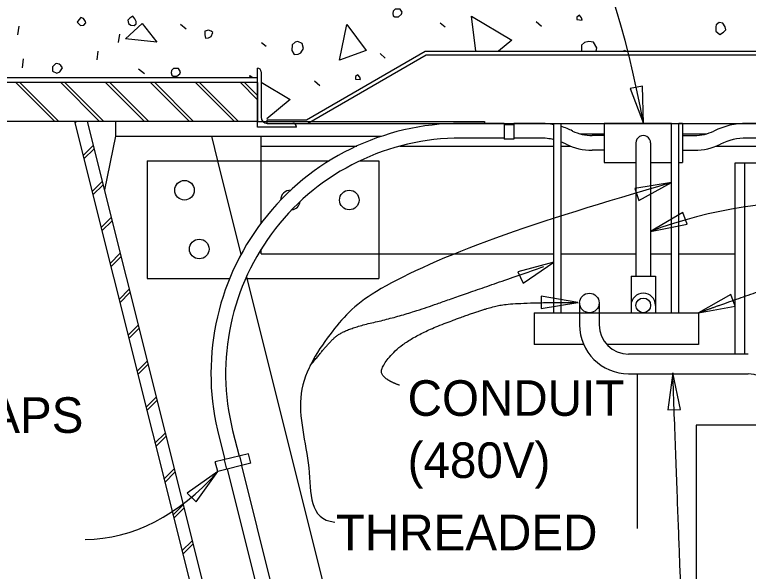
# Model space of a CAD drawing. Extents: x -1660015.2 to -1659984.9, y 2580594.2 to 2580616.7.
# Drawn here: x -1660013.123 to -1660010.005, y 2580601.136 to 2580603.502 of the extents above; entities that cross this region are included whole.
import ezdxf

# ---------------------------------------------------------------- set-up
doc = ezdxf.new("R2010")
doc.units = 0
for name, color, linetype in [('Default', 7, 'Continuous'), ('Miscellaneous', 7, 'Continuous'), ('SheetLines_dp', 7, 'Continuous'), ('SteelGirder', 7, 'Continuous')]:
    doc.layers.add(name, color=color, linetype=linetype)

msp = doc.modelspace()

# ---------------------------------------------------------------- linework, layer by layer
at = {"layer": 'Default'}
for p, q in [((-1660011.0429, 2580603.0403), (-1660011.2268, 2580603.0403)), ((-1660010.8905, 2580603.0403), (-1660011.0012, 2580603.0403)), ((-1660010.6182, 2580603.0404), (-1660010.6182, 2580602.8737)), ((-1660010.3317, 2580603.0404), (-1660010.6182, 2580603.0404)), ((-1660010.2849, 2580603.0404), (-1660010.3005, 2580603.0404)), ((-1660010.2849, 2580603.0404), (-1660010.2849, 2580602.8737)), ((-1660009.6587, 2580603.0404), (-1660010.0129, 2580603.0404)), ((-1660011.0429, 2580602.9779), (-1660011.2268, 2580602.9779)), ((-1660010.8902, 2580602.9779), (-1660011.0012, 2580602.9779)), ((-1660010.6182, 2580602.9883), (-1660010.6686, 2580602.9883)), ((-1660010.2849, 2580602.9883), (-1660010.2345, 2580602.9883)), ((-1660009.6587, 2580602.9779), (-1660010.013, 2580602.9779)), ((-1660012.0762, 2580602.6162), (-1660012.0762, 2580602.9437)), ((-1660010.4828, 2580602.957), (-1660010.4828, 2580602.3908)), ((-1660010.4203, 2580602.957), (-1660010.4203, 2580602.3908)), ((-1660010.6182, 2580602.9258), (-1660010.6686, 2580602.9258)), ((-1660010.2849, 2580602.9258), (-1660010.2345, 2580602.9258)), ((-1660012.2611, 2580602.8812), (-1660012.1615, 2580602.4831)), ((-1660010.6182, 2580602.8737), (-1660010.4828, 2580602.8737)), ((-1660010.4203, 2580602.8737), (-1660010.3317, 2580602.8737)), ((-1660010.3005, 2580602.8737), (-1660010.2849, 2580602.8737)), ((-1660010.0631, 2580602.8708), (-1660010.0631, 2580602.0589)), ((-1660009.9277, 2580602.8708), (-1660010.0631, 2580602.8708)), ((-1660010.0215, 2580602.8708), (-1660010.0215, 2580602.0589)), ((-1660012.0762, 2580602.4853), (-1660012.0762, 2580602.5057)), ((-1660012.0762, 2580602.4853), (-1660011.5762, 2580602.4853)), ((-1660012.1381, 2580602.3896), (-1660012.136, 2580602.3812)), ((-1660010.5036, 2580602.3908), (-1660010.3995, 2580602.3908)), ((-1660010.5036, 2580602.3908), (-1660010.5036, 2580602.2353)), ((-1660010.3995, 2580602.3908), (-1660010.3995, 2580602.2353)), ((-1660010.7223, 2580602.277), (-1660010.7223, 2580602.184)), ((-1660010.639, 2580602.277), (-1660010.639, 2580602.1841)), ((-1660010.9151, 2580602.2353), (-1660010.2172, 2580602.2353)), ((-1660010.9151, 2580602.2353), (-1660010.9151, 2580602.0999)), ((-1660010.2172, 2580602.2353), (-1660010.2172, 2580602.0999)), ((-1660010.7046, 2580602.0999), (-1660010.9151, 2580602.0999)), ((-1660010.2172, 2580602.0999), (-1660010.6064, 2580602.0999)), ((-1660010.0052, 2580602.0589), (-1660010.514, 2580602.0591)), ((-1660010.5141, 2580601.9757), (-1660010.0053, 2580601.9755)), ((-1660012.197, 2580601.7353), (-1660012.1697, 2580601.6264)), ((-1660012.2542, 2580601.7069), (-1660012.2303, 2580601.6112)), ((-1660012.2202, 2580601.5708), (-1660011.7218, 2580599.577)), ((-1660012.1596, 2580601.5859), (-1660011.6612, 2580599.5922))]:
    msp.add_line(p, q, dxfattribs=at)
msp.add_lwpolyline([(-1660009.2275, 2580601.7577), (-1660010.2275, 2580601.7577), (-1660010.2275, 2580599.0077), (-1660009.2275, 2580599.0077)], close=True, dxfattribs=at)
for centre, radius in [((-1660010.6807, 2580602.277), 0.0416), ((-1660010.4516, 2580602.2666), 0.0312)]:
    msp.add_circle(centre, radius, dxfattribs=at)
for centre, radius, start, end in [((-1660011.2268, 2580601.9779), 1.0625, 90.0002, 194.7729), ((-1660010.8908, 2580602.7279), 0.3125, 79.1097, 89.9466), ((-1660010.0123, 2580602.7279), 0.3125, 90.0002, 116.3886), ((-1660010.8908, 2580602.7279), 0.3125, 63.6116, 73.2157), ((-1660010.6686, 2580603.1758), 0.1875, 243.6116, 270.0001), ((-1660010.2345, 2580603.1758), 0.1875, 270.0001, 296.3886), ((-1660011.2268, 2580601.9779), 1, 90.0002, 194.0354), ((-1660010.8908, 2580602.7279), 0.25, 76.3399, 89.8674), ((-1660010.4516, 2580602.957), 0.0312, 359.9876, 180.0001), ((-1660010.0123, 2580602.7279), 0.25, 90.0002, 116.3886), ((-1660010.8908, 2580602.7279), 0.25, 63.6116, 68.8407), ((-1660010.6686, 2580603.1758), 0.25, 243.6116, 270.0001), ((-1660010.2345, 2580603.1758), 0.25, 270.0001, 296.3886), ((-1660010.4516, 2580602.2666), 0.052, 0.0163, 179.7051), ((-1660010.514, 2580602.184), 0.2083, 180, 269.9792), ((-1660010.514, 2580602.1841), 0.125, 180, 269.9792), ((-1660010.0053, 2580601.8505), 0.125, 0, 89.9792)]:
    msp.add_arc(centre, radius, start, end, dxfattribs=at)
at = {"layer": 'Miscellaneous'}
for p, q in [((-1660011.3147, 2580603.4678), (-1660011.2944, 2580603.4499)), ((-1660010.9073, 2580603.4734), (-1660010.8839, 2580603.4538)), ((-1660013.1101, 2580603.4164), (-1660013.1046, 2580603.454)), ((-1660012.4183, 2580603.4619), (-1660012.3949, 2580603.4423)), ((-1660012.682, 2580603.3835), (-1660012.6759, 2580603.4188)), ((-1660012.0737, 2580603.3835), (-1660012.0541, 2580603.368)), ((-1660012.7735, 2580603.3098), (-1660012.7681, 2580603.3475)), ((-1660011.8834, 2580603.0559), (-1660011.3782, 2580603.3476)), ((-1660011.3782, 2580603.3476), (-1660006.558, 2580603.3477)), ((-1660013.0907, 2580603.2766), (-1660013.0853, 2580603.3143)), ((-1660011.8792, 2580603.0403), (-1660011.374, 2580603.332)), ((-1660011.5696, 2580603.3374), (-1660011.5487, 2580603.3171)), ((-1660011.374, 2580603.332), (-1660006.558, 2580603.3321)), ((-1660012.5976, 2580603.2715), (-1660012.5718, 2580603.2526)), ((-1660012.0918, 2580603.0247), (-1660012.0917, 2580603.2747)), ((-1660012.0761, 2580603.2591), (-1660012.0761, 2580603.0664)), ((-1660013.5994, 2580603.2354), (-1660012.0917, 2580603.2354)), ((-1660011.849, 2580603.2211), (-1660011.8257, 2580603.2015)), ((-1660012.9534, 2580603.0479), (-1660013.1202, 2580603.2147)), ((-1660012.9358, 2580603.0479), (-1660013.1025, 2580603.2147)), ((-1660012.7625, 2580603.0479), (-1660012.9292, 2580603.2147)), ((-1660012.7449, 2580603.0479), (-1660012.9116, 2580603.2147)), ((-1660012.5716, 2580603.0479), (-1660012.7383, 2580603.2147)), ((-1660012.5539, 2580603.0479), (-1660012.7207, 2580603.2147)), ((-1660012.3807, 2580603.0479), (-1660012.5474, 2580603.2147)), ((-1660012.363, 2580603.0479), (-1660012.5297, 2580603.2147)), ((-1660012.1898, 2580603.0479), (-1660012.3565, 2580603.2147)), ((-1660012.1721, 2580603.0479), (-1660012.3388, 2580603.2147)), ((-1660012.0918, 2580603.1409), (-1660012.1656, 2580603.2147)), ((-1660012.0918, 2580603.1586), (-1660012.1479, 2580603.2147)), ((-1660012.8671, 2580603.0418), (-1660012.861, 2580603.0479)), ((-1660012.0501, 2580603.0559), (-1660011.8835, 2580603.0559)), ((-1660012.0501, 2580603.0403), (-1660012.0501, 2580603.0559)), ((-1660012.0501, 2580603.0403), (-1660006.558, 2580603.0403)), ((-1660012.0501, 2580603.0403), (-1660011.9407, 2580603.0403)), ((-1660011.9251, 2580603.0247), (-1660012.0918, 2580603.0247)), ((-1660012.8325, 2580602.9032), (-1660012.7895, 2580602.9462)), ((-1660012.829, 2580602.8891), (-1660012.786, 2580602.932)), ((-1660012.7943, 2580602.7505), (-1660012.7513, 2580602.7934)), ((-1660012.7908, 2580602.7363), (-1660012.7478, 2580602.7793)), ((-1660012.7561, 2580602.5977), (-1660012.7132, 2580602.6407)), ((-1660012.7526, 2580602.5836), (-1660012.7096, 2580602.6265)), ((-1660012.7179, 2580602.445), (-1660012.675, 2580602.488)), ((-1660012.7144, 2580602.4309), (-1660012.6714, 2580602.4738)), ((-1660012.6798, 2580602.2923), (-1660012.6368, 2580602.3352)), ((-1660012.6762, 2580602.2781), (-1660012.6333, 2580602.3211)), ((-1660012.6416, 2580602.1395), (-1660012.5986, 2580602.1825)), ((-1660012.638, 2580602.1254), (-1660012.5951, 2580602.1683)), ((-1660012.6034, 2580601.9868), (-1660012.5604, 2580602.0298)), ((-1660012.5998, 2580601.9726), (-1660012.5569, 2580602.0156)), ((-1660012.5652, 2580601.8341), (-1660012.5222, 2580601.877)), ((-1660012.5617, 2580601.8199), (-1660012.5187, 2580601.8629)), ((-1660012.527, 2580601.6813), (-1660012.4841, 2580601.7243)), ((-1660012.5235, 2580601.6672), (-1660012.4805, 2580601.7101)), ((-1660012.4888, 2580601.5286), (-1660012.4459, 2580601.5715)), ((-1660012.4853, 2580601.5144), (-1660012.4423, 2580601.5574)), ((-1660012.4506, 2580601.3758), (-1660012.4077, 2580601.4188)), ((-1660012.4471, 2580601.3617), (-1660012.4042, 2580601.4047)), ((-1660012.4125, 2580601.2231), (-1660012.3695, 2580601.2661)), ((-1660012.4089, 2580601.209), (-1660012.366, 2580601.2519))]:
    msp.add_line(p, q, dxfattribs=at)
for points in [[(-1660012.6391, 2580603.4649), (-1660012.6292, 2580603.4572), (-1660012.6159, 2580603.4556), (-1660012.6075, 2580603.463), (-1660012.6077, 2580603.4733), (-1660012.6133, 2580603.4847), (-1660012.6214, 2580603.4955), (-1660012.6346, 2580603.4868), (-1660012.643, 2580603.4794), (-1660012.6391, 2580603.4649)], [(-1660011.5141, 2580603.4972), (-1660011.508, 2580603.4936), (-1660011.4922, 2580603.4927), (-1660011.4796, 2580603.5038), (-1660011.4768, 2580603.5124), (-1660011.4855, 2580603.5255), (-1660011.5061, 2580603.5252), (-1660011.5144, 2580603.5178), (-1660011.5167, 2580603.5068), (-1660011.5141, 2580603.4972)], [(-1660011.1636, 2580603.3476), (-1660011.1824, 2580603.4955), (-1660011.0102, 2580603.3941), (-1660011.0665, 2580603.3476)], [(-1660010.7334, 2580603.4812), (-1660010.7121, 2580603.4791), (-1660010.7147, 2580603.4888), (-1660010.7228, 2580603.4996), (-1660010.7335, 2580603.4915), (-1660010.7334, 2580603.4812)], [(-1660012.8581, 2580603.4709), (-1660012.8439, 2580603.4566), (-1660012.8288, 2580603.4581), (-1660012.8211, 2580603.4679), (-1660012.8223, 2580603.4727), (-1660012.8311, 2580603.4859), (-1660012.8427, 2580603.4906), (-1660012.8504, 2580603.4808), (-1660012.8581, 2580603.4709)], [(-1660012.6525, 2580603.3992), (-1660012.5821, 2580603.4646), (-1660012.5195, 2580603.3857), (-1660012.6525, 2580603.3992)], [(-1660010.1428, 2580603.4505), (-1660010.1431, 2580603.4323), (-1660010.1265, 2580603.4186), (-1660010.1109, 2580603.428), (-1660010.1007, 2580603.4385), (-1660010.104, 2580603.4505), (-1660010.1133, 2580603.4662), (-1660010.1298, 2580603.4695), (-1660010.1423, 2580603.4584), (-1660010.1428, 2580603.4505)], [(-1660012.3157, 2580603.417), (-1660012.3118, 2580603.4025), (-1660012.299, 2580603.4033), (-1660012.2876, 2580603.409), (-1660012.2818, 2580603.426), (-1660012.2886, 2580603.432), (-1660012.3002, 2580603.4366), (-1660012.3147, 2580603.4328), (-1660012.3157, 2580603.417)], [(-1660011.7432, 2580603.309), (-1660011.7112, 2580603.4599), (-1660011.6299, 2580603.3497), (-1660011.7432, 2580603.309)], [(-1660011.9444, 2580603.3741), (-1660011.9458, 2580603.3504), (-1660011.9358, 2580603.3324), (-1660011.9183, 2580603.3345), (-1660011.9068, 2580603.3402), (-1660011.8962, 2580603.3585), (-1660011.9021, 2580603.3803), (-1660011.9198, 2580603.3885), (-1660011.9319, 2580603.3852), (-1660011.9444, 2580603.3741)], [(-1660010.6513, 2580603.3476), (-1660010.6495, 2580603.3613), (-1660010.6638, 2580603.3859), (-1660010.6827, 2580603.3887), (-1660010.702, 2580603.3835), (-1660010.7145, 2580603.3724)], [(-1660010.7145, 2580603.3724), (-1660010.7138, 2580603.3476)], [(-1660010.5336, 2580603.3476), (-1660010.5329, 2580603.3512), (-1660010.5244, 2580603.3476)], [(-1660012.9622, 2580603.28), (-1660012.9625, 2580603.2618), (-1660012.9448, 2580603.2536), (-1660012.931, 2580603.2599), (-1660012.9197, 2580603.2758), (-1660012.9278, 2580603.2866), (-1660012.9345, 2580603.2926), (-1660012.9455, 2580603.2948), (-1660012.9503, 2580603.2935), (-1660012.9622, 2580603.28)], [(-1660012.4559, 2580603.2448), (-1660012.4497, 2580603.2413), (-1660012.434, 2580603.2403), (-1660012.4214, 2580603.2515), (-1660012.4185, 2580603.26), (-1660012.4272, 2580603.2732), (-1660012.4479, 2580603.2729), (-1660012.4562, 2580603.2654), (-1660012.4585, 2580603.2545), (-1660012.4559, 2580603.2448)], [(-1660011.6751, 2580603.2288), (-1660011.6539, 2580603.2268), (-1660011.6565, 2580603.2364), (-1660011.6645, 2580603.2472), (-1660011.6753, 2580603.2392), (-1660011.6751, 2580603.2288)], [(-1660012.1232, 2580603.2354), (-1660012.1241, 2580603.2431), (-1660012.1111, 2580603.2354)], [(-1660012.0761, 2580603.2148), (-1660011.952, 2580603.1417), (-1660012.051, 2580603.0601)]]:
    msp.add_lwpolyline(points, dxfattribs=at)
for centre, radius, start, end in [((-1660012.0917, 2580603.2591), 0.0156, 359.9953, 89.9953), ((-1660012.0501, 2580603.0664), 0.026, 179.9953, 269.9953), ((-1660011.9407, 2580603.0247), 0.0156, 359.9953, 89.9953)]:
    msp.add_arc(centre, radius, start, end, dxfattribs=at)
at = {"layer": 'SheetLines_dp'}
for points in [[(-1660010.4504, 2580603.0403), (-1660010.4553, 2580603.1986), (-1660010.5072, 2580603.1882)], [(-1660010.3316, 2580602.7885), (-1660010.488, 2580602.7629), (-1660010.4708, 2580602.7128)], [(-1660010.4203, 2580602.5812), (-1660010.2647, 2580602.6113), (-1660010.2833, 2580602.6609)], [(-1660010.8317, 2580602.451), (-1660010.9847, 2580602.4099), (-1660010.9626, 2580602.3618)], [(-1660010.2171, 2580602.2353), (-1660010.0612, 2580602.2634), (-1660010.0792, 2580602.3132)], [(-1660010.7294, 2580602.2795), (-1660010.8856, 2580602.3059), (-1660010.8856, 2580602.253)], [(-1660010.3262, 2580601.9795), (-1660010.3469, 2580601.8224), (-1660010.294, 2580601.8244)], [(-1660012.2606, 2580601.5607), (-1660012.3899, 2580601.4692), (-1660012.3526, 2580601.4317)]]:
    msp.add_lwpolyline(points, close=True, dxfattribs=at)
msp.add_arc((-1660009.7245, 2580600.7276), 1.9799, 86.9707, 110.5746, dxfattribs=at)
for centre, major_axis, ratio, start_param, end_param in [((-1660011.1248, 2580601.8147), (0.0332, -2.5173), 0.313255, 2.075166, 3.141607), ((-1660012.8379, 2580602.8656), (-0.0144, 1.5941), 0.622544, 3.141613, 3.747853)]:
    msp.add_ellipse(centre, major_axis=major_axis, ratio=ratio, start_param=start_param, end_param=end_param, dxfattribs=at)
for points, degree in [([(-1660010.3316, 2580602.7885), (-1660010.6273, 2580602.702), (-1660011.1173, 2580602.5539), (-1660011.6277, 2580602.3242), (-1660011.7655, 2580602.1761), (-1660011.9544, 2580601.9004), (-1660011.8503, 2580601.5782), (-1660011.8746, 2580601.3562), (-1660011.7623, 2580601.346)], 3), ([(-1660011.8675, 2580602.0098), (-1660011.8012, 2580602.0944), (-1660011.7247, 2580602.1659), (-1660011.4746, 2580602.222), (-1660011.2143, 2580602.3139), (-1660010.8738, 2580602.4317)], 2), ([(-1660010.2171, 2580602.2353), (-1660010.0702, 2580602.2883), (-1660009.6473, 2580602.4352), (-1660009.2337, 2580602.3615)], 2), ([(-1660011.4874, 2580601.9272), (-1660011.5461, 2580601.9476), (-1660011.5767, 2580601.9986), (-1660011.4516, 2580602.1314), (-1660011.1275, 2580602.2539), (-1660011.0025, 2580602.2795), (-1660010.7294, 2580602.2795)], 2), ([(-1660012.6865, 2580600.4529), (-1660011.2138, 2580600.4631), (-1660010.2701, 2580600.5141), (-1660010.2905, 2580601.0094), (-1660010.3262, 2580601.9795)], 2)]:
    msp.add_open_spline(points, degree=degree, dxfattribs=at)
at = {"layer": 'SteelGirder'}
for p, q in [((-1660012.0918, 2580603.2146), (-1660013.5918, 2580603.2146)), ((-1660012.0918, 2580603.2146), (-1660012.0918, 2580603.0479)), ((-1660012.0918, 2580603.0479), (-1660013.5918, 2580603.0479)), ((-1660012.8687, 2580603.0479), (-1660011.3062, 2580596.798)), ((-1660012.815, 2580603.0479), (-1660011.2525, 2580596.798)), ((-1660012.6931, 2580602.9854), (-1660012.6931, 2580603.0479)), ((-1660012.0944, 2580603.0479), (-1660012.0917, 2580603.0505)), ((-1660012.0944, 2580603.0479), (-1660012.0917, 2580603.0505)), ((-1660012.0918, 2580603.0479), (-1660011.1272, 2580603.0479)), ((-1660011.1272, 2580603.0479), (-1660011.1272, 2580603.0404)), ((-1660011.0429, 2580603.0403), (-1660011.0429, 2580602.9727)), ((-1660011.0429, 2580603.0403), (-1660011.0012, 2580603.0403)), ((-1660011.0429, 2580603.0352), (-1660011.0012, 2580603.0352)), ((-1660011.0012, 2580603.0403), (-1660011.0012, 2580602.9727)), ((-1660010.8318, 2580602.2353), (-1660010.8318, 2580603.0403)), ((-1660010.8006, 2580602.2353), (-1660010.8006, 2580603.0403)), ((-1660010.3317, 2580602.2353), (-1660010.3317, 2580603.0403)), ((-1660010.3005, 2580602.2353), (-1660010.3005, 2580603.0403)), ((-1660012.6953, 2580602.9854), (-1660012.7423, 2580602.7576)), ((-1660012.6931, 2580602.9854), (-1660011.5642, 2580602.9854)), ((-1660012.2871, 2580602.9854), (-1660012.261, 2580602.8812)), ((-1660012.0762, 2580602.8708), (-1660012.0762, 2580602.9854)), ((-1660011.0012, 2580602.9727), (-1660011.0429, 2580602.9727)), ((-1660010.7206, 2580602.9956), (-1660010.6182, 2580602.9956)), ((-1660010.2849, 2580602.9956), (-1660010.1826, 2580602.9956)), ((-1660012.0762, 2580602.9437), (-1660011.6696, 2580602.9437)), ((-1660011.486, 2580602.9437), (-1660010.8318, 2580602.9437)), ((-1660010.8006, 2580602.9437), (-1660010.7616, 2580602.9437)), ((-1660010.1415, 2580602.9437), (-1660007.6465, 2580602.9437)), ((-1660012.5605, 2580602.8812), (-1660012.5605, 2580602.3812)), ((-1660012.5605, 2580602.8812), (-1660011.7862, 2580602.8812)), ((-1660011.6557, 2580602.8812), (-1660011.5762, 2580602.8812)), ((-1660011.5762, 2580602.8812), (-1660011.5762, 2580602.3812)), ((-1660011.5762, 2580602.4853), (-1660010.8318, 2580602.4853)), ((-1660010.8006, 2580602.4853), (-1660010.4828, 2580602.4853)), ((-1660010.4203, 2580602.4853), (-1660010.3317, 2580602.4853)), ((-1660010.3005, 2580602.4853), (-1660010.0631, 2580602.4853)), ((-1660012.5605, 2580602.3812), (-1660012.2098, 2580602.3812)), ((-1660012.1419, 2580602.3812), (-1660011.5762, 2580602.3812)), ((-1660012.136, 2580602.3812), (-1660011.1489, 2580598.4333)), ((-1660012.1293, 2580601.6365), (-1660012.2707, 2580601.6011)), ((-1660012.1675, 2580601.6269), (-1660012.1574, 2580601.5865)), ((-1660012.1192, 2580601.596), (-1660012.1293, 2580601.6365)), ((-1660012.2606, 2580601.5607), (-1660012.2707, 2580601.6011)), ((-1660012.1192, 2580601.596), (-1660012.2606, 2580601.5607)), ((-1660012.2325, 2580601.6107), (-1660012.2224, 2580601.5702))]:
    msp.add_line(p, q, dxfattribs=at)
msp.add_lwpolyline([(-1660010.4775, 2580601.9757), (-1660010.4775, 2580601.3183)], dxfattribs=at)
for centre in [(-1660012.4016, 2580602.7562), (-1660011.7012, 2580602.7145), (-1660012.3391, 2580602.5062)]:
    msp.add_circle(centre, 0.0417, dxfattribs=at)
for start, end in [(88.5209, 180.5137), (277.7816, 351.253)]:
    msp.add_arc((-1660011.9512, 2580602.7145), 0.0417, start, end, dxfattribs=at)

# ---------------------------------------------------------------- texts
at = {"layer": 'SheetLines_dp'}
for s, p in [('CONDUIT', (-1660011.4533, 2580601.7973)), ('SINGLE HOLE STRAPS', (-1660015.0447, 2580601.725)), ('(480V)', (-1660011.4533, 2580601.5333)), ('THREADED', (-1660011.7585, 2580601.2261))]:
    msp.add_text(s, height=0.1512, dxfattribs=at).set_placement(p)

doc.saveas('drawing.dxf')
